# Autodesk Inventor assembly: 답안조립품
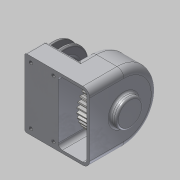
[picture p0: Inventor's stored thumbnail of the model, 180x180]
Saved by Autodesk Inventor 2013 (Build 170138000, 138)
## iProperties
Created: 2015-02
Part Number: 답안조립품
Document SubType Name: Assembly
Designer: Administrator
Author: Administrator
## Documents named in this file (14)
- C:\Users\Administrator\Desktop\450216V1009\답안조립품.iam
- C:\Users\Administrator\Desktop\450216V1009\축.ipt
- C:\Users\Administrator\Desktop\450216V1009\키4x4.ipt
- C:\Users\Administrator\Desktop\450216V1009\키5x5.ipt
- C:\Users\Administrator\Desktop\450216V1009\스퍼기어.ipt
- C:\Users\Administrator\Desktop\450216V1009\베어링 6001.ipt
- C:\Users\Administrator\Desktop\450216V1009\V-벨트풀리.ipt
- C:\Users\Administrator\Desktop\450216V1009\와샤.ipt
- C:\Users\Administrator\Desktop\450216V1009\M5x0.8.ipt
- M5x0.8.ipt
- C:\Users\Administrator\Desktop\450216V1009\본체.ipt
- C:\Users\Administrator\Desktop\450216V1009\오일실.ipt
- C:\Users\Administrator\Desktop\450216V1009\축커버.ipt
- C:\Users\Administrator\Desktop\450216V1009\M3x0.5.ipt
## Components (6 placed, 3 different names)
1. V-벨트풀리:1 — 각도:4
2. M5x0.8:1 — 각도:5
3. M3x0.5:1
4. M3x0.5:2
5. M3x0.5:3
6. M3x0.5:4
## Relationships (2: Angle 2)
- 각도:4 [Angle]: V-벨트풀리:1
- 각도:5 [Angle]: M5x0.8:1
